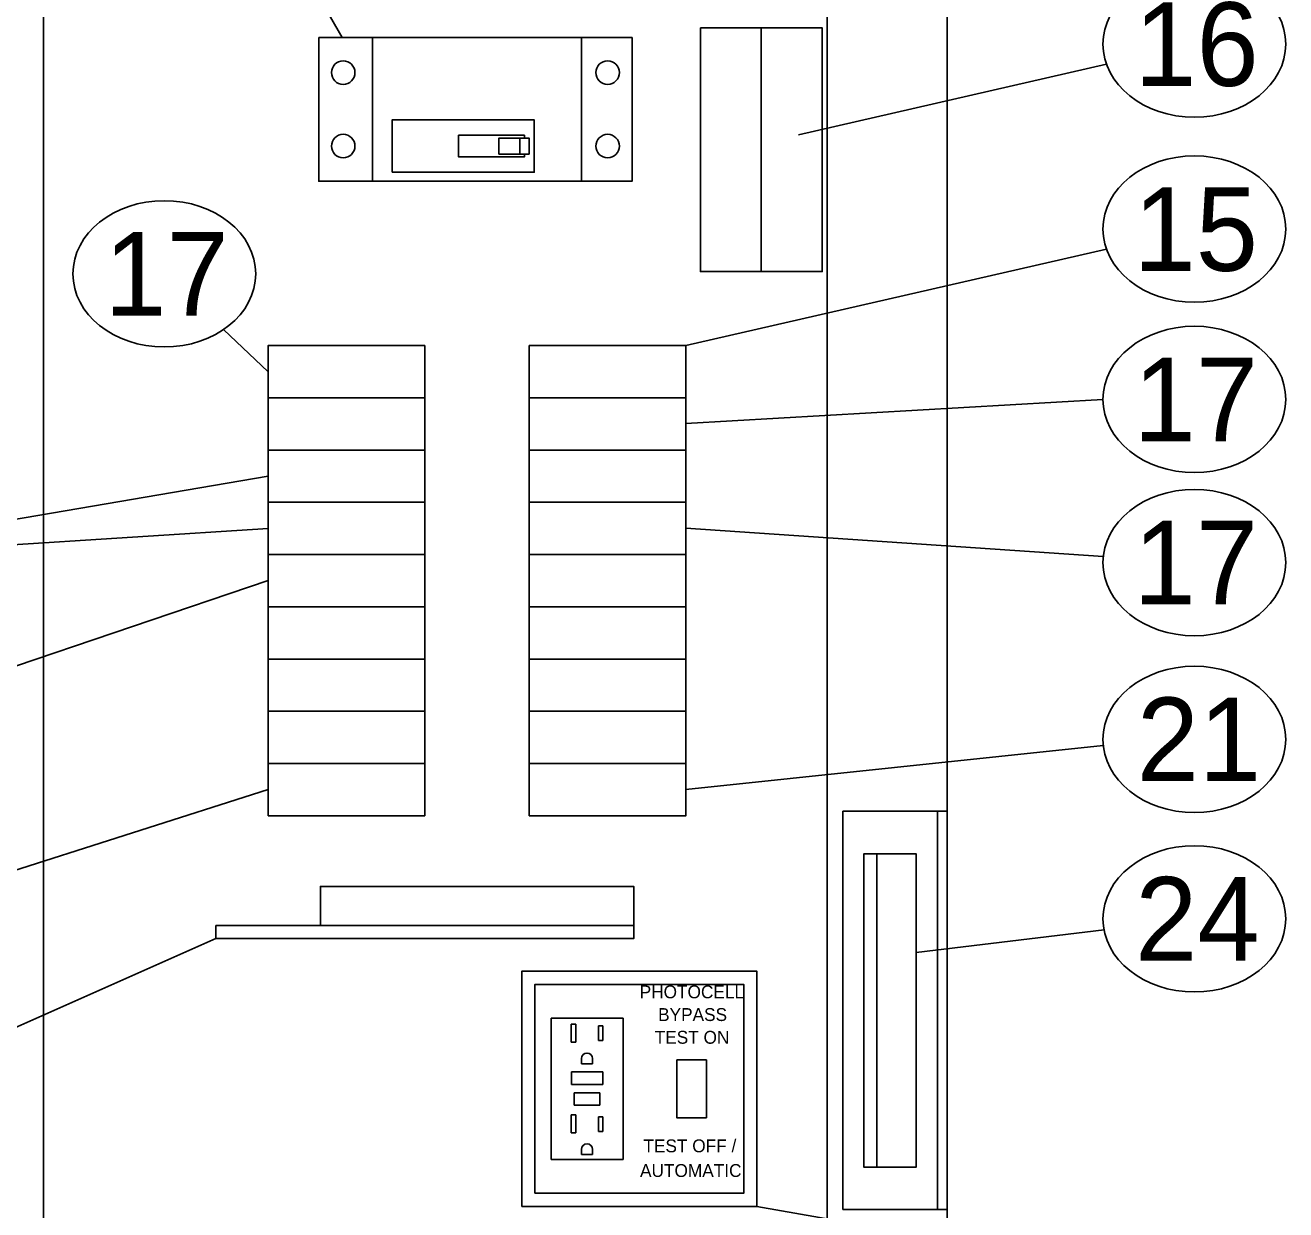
# Model space of a CAD drawing. Extents: x 99862 to 103680, y 99470 to 105076.
# Drawn here: x 102200.2 to 102441.5, y 104648.7 to 104875.4 of the extents above; entities that cross this region are included whole.
import ezdxf

# ---------------------------------------------------------------- set-up
doc = ezdxf.new("R2010")
doc.units = 0
for name, color, linetype in [('Level 1', 7, 'Continuous'), ('Level 15', 7, 'Continuous'), ('Level 20', 7, 'Continuous'), ('Level 40', 7, 'Continuous')]:
    doc.layers.add(name, color=color, linetype=linetype)

msp = doc.modelspace()

# ---------------------------------------------------------------- linework, layer by layer
at = {"layer": 'Level 1'}
for p, q in [((102203.66, 104537.04), (102203.66, 104897.04)), ((102353.66, 104897.04), (102353.66, 104537.04)), ((102294.86, 104853.79), (102294.86, 104850.73)), ((102246.66, 104804.08), (102276.66, 104804.08)), ((102296.66, 104804.08), (102326.66, 104804.08)), ((102296.66, 104784.08), (102326.66, 104784.08)), ((102356.66, 104648.69), (102356.66, 104724.94)), ((102356.66, 104724.94), (102376.66, 104724.94)), ((102374.79, 104648.69), (102374.79, 104724.94)), ((102376.66, 104648.69), (102376.66, 104724.94)), ((102300.84, 104658.31), (102300.84, 104685.31)), ((102300.84, 104685.31), (102314.62, 104685.31)), ((102304.68, 104684.2), (102305.54, 104684.2)), ((102304.68, 104684.2), (102304.68, 104680.74)), ((102305.54, 104684.2), (102305.54, 104680.74)), ((102309.9, 104683.84), (102309.9, 104681.03)), ((102309.9, 104683.84), (102310.77, 104683.84)), ((102310.77, 104683.84), (102310.77, 104681.03)), ((102314.62, 104685.31), (102314.62, 104658.31)), ((102304.68, 104680.74), (102305.54, 104680.74)), ((102309.9, 104681.03), (102310.77, 104681.03)), ((102306.65, 104677.6), (102306.65, 104676.58)), ((102306.65, 104676.58), (102308.78, 104676.58)), ((102308.78, 104677.6), (102308.78, 104676.58)), ((102304.73, 104675.08), (102310.73, 104675.08)), ((102304.73, 104675.08), (102304.73, 104672.62)), ((102310.73, 104675.08), (102310.73, 104672.62)), ((102304.73, 104672.62), (102310.73, 104672.62)), ((102305.23, 104671.06), (102305.23, 104668.66)), ((102305.23, 104671.06), (102310.19, 104671.06)), ((102310.19, 104671.06), (102310.19, 104668.66)), ((102304.68, 104666.82), (102305.54, 104666.82)), ((102304.68, 104666.82), (102304.68, 104663.37)), ((102305.23, 104668.66), (102310.19, 104668.66)), ((102305.54, 104666.82), (102305.54, 104663.37)), ((102309.9, 104666.47), (102309.9, 104663.66)), ((102309.9, 104666.47), (102310.77, 104666.47)), ((102310.77, 104666.47), (102310.77, 104663.66)), ((102304.68, 104663.37), (102305.54, 104663.37)), ((102309.9, 104663.66), (102310.77, 104663.66)), ((102306.65, 104660.22), (102306.65, 104659.21)), ((102306.65, 104659.21), (102308.78, 104659.21)), ((102308.78, 104660.22), (102308.78, 104659.21)), ((102314.62, 104658.31), (102300.84, 104658.31)), ((102356.66, 104648.69), (102376.66, 104648.69))]:
    msp.add_line(p, q, dxfattribs=at)
for points in [[(102256.35, 104873.04), (102316.35, 104873.04), (102316.35, 104845.54), (102256.35, 104845.54)], [(102266.66, 104873.04), (102306.66, 104873.04), (102306.66, 104845.54), (102266.66, 104845.54)], [(102270.41, 104847.26), (102297.6, 104847.26), (102297.6, 104857.26), (102270.41, 104857.26)], [(102296.62, 104850.73), (102290.86, 104850.73), (102290.86, 104853.79), (102296.62, 104853.79)], [(102246.66, 104794.08), (102276.66, 104794.08), (102276.66, 104814.08), (102246.66, 104814.08)], [(102296.66, 104794.08), (102326.66, 104794.08), (102326.66, 104814.08), (102296.66, 104814.08)], [(102246.66, 104784.08), (102276.66, 104784.08), (102276.66, 104794.08), (102246.66, 104794.08)], [(102296.66, 104774.08), (102326.66, 104774.08), (102326.66, 104794.08), (102296.66, 104794.08)], [(102246.66, 104774.08), (102276.66, 104774.08), (102276.66, 104784.08), (102246.66, 104784.08)], [(102246.66, 104764.08), (102276.66, 104764.08), (102276.66, 104774.08), (102246.66, 104774.08)], [(102296.66, 104764.08), (102326.66, 104764.08), (102326.66, 104774.08), (102296.66, 104774.08)], [(102246.66, 104754.08), (102276.66, 104754.08), (102276.66, 104764.08), (102246.66, 104764.08)], [(102296.66, 104754.08), (102326.66, 104754.08), (102326.66, 104764.08), (102296.66, 104764.08)], [(102246.66, 104744.08), (102276.66, 104744.08), (102276.66, 104754.08), (102246.66, 104754.08)], [(102296.66, 104744.08), (102326.66, 104744.08), (102326.66, 104754.08), (102296.66, 104754.08)], [(102246.66, 104734.08), (102276.66, 104734.08), (102276.66, 104744.08), (102246.66, 104744.08)], [(102296.66, 104734.08), (102326.66, 104734.08), (102326.66, 104744.08), (102296.66, 104744.08)], [(102246.66, 104724.08), (102276.66, 104724.08), (102276.66, 104734.08), (102246.66, 104734.08)], [(102296.66, 104724.08), (102326.66, 104724.08), (102326.66, 104734.08), (102296.66, 104734.08)], [(102360.72, 104716.81), (102360.72, 104656.81), (102370.72, 104656.81), (102370.72, 104716.81)], [(102363.22, 104656.81), (102363.22, 104716.81), (102360.72, 104716.81), (102360.72, 104656.81)], [(102316.66, 104703.06), (102236.66, 104703.06), (102236.66, 104700.56), (102316.66, 104700.56)], [(102295.23, 104649.31), (102340.23, 104649.31), (102340.23, 104694.31), (102295.23, 104694.31)], [(102297.73, 104651.81), (102337.73, 104651.81), (102337.73, 104691.81), (102297.73, 104691.81)], [(102324.89, 104677.34), (102324.89, 104666.27), (102330.56, 104666.27), (102330.56, 104677.34)]]:
    msp.add_lwpolyline(points, close=True, dxfattribs=at)
for points in [[(102295.73, 104853.79), (102295.73, 104854.34), (102283.14, 104854.34), (102283.14, 104850.18), (102295.73, 104850.18), (102295.73, 104850.73)], [(102256.66, 104700.56), (102316.66, 104700.56), (102316.66, 104710.56), (102256.66, 104710.56), (102256.66, 104703.06)]]:
    msp.add_lwpolyline(points, dxfattribs=at)
for centre in [(102261.04, 104866.32), (102311.66, 104866.32), (102261.04, 104852.26), (102311.66, 104852.26)]:
    msp.add_circle(centre, 2.25, dxfattribs=at)
for centre in [(102307.72, 104677.6), (102307.72, 104660.22)]:
    msp.add_arc(centre, 1.06, 360, 180, dxfattribs=at)
at = {"layer": 'Level 15'}
for p, q in [((102214.75, 104953.33), (102260.87, 104873.04)), ((102407.16, 104867.93), (102348.18, 104854.42)), ((102407.16, 104832.53), (102326.66, 104814.08)), ((102246.66, 104809.08), (102238.12, 104817.14)), ((102406.48, 104803.77), (102326.66, 104799.14)), ((102246.66, 104789.08), (102152.68, 104773.08)), ((102246.66, 104779.08), (102152.68, 104773.08)), ((102406.54, 104773.72), (102326.66, 104779.14)), ((102246.66, 104769.08), (102142.14, 104733.7)), ((102406.54, 104737.52), (102326.66, 104729.08)), ((102246.66, 104729.08), (102142.28, 104695.84)), ((102236.66, 104700.56), (102141.33, 104658.26)), ((102370.72, 104697.9), (102406.68, 104702.26)), ((102340.23, 104649.31), (102406.88, 104637.63))]:
    msp.add_line(p, q, dxfattribs=at)
at = {"layer": 'Level 20'}
for centre in [(102423.98, 104871.78), (102423.98, 104836.38), (102226.79, 104827.81), (102423.98, 104803.77), (102423.98, 104772.53), (102423.98, 104738.7), (102423.98, 104704.35)]:
    msp.add_ellipse(centre, major_axis=(-17.5, 0), ratio=0.8, dxfattribs=at)
at = {"layer": 'Level 40'}
for p, q in [((102376.66, 104902.94), (102376.66, 104497.94)), ((102341.08, 104874.88), (102341.08, 104828.25))]:
    msp.add_line(p, q, dxfattribs=at)
msp.add_lwpolyline([(102329.42, 104874.88), (102329.42, 104828.25), (102352.74, 104828.25), (102352.74, 104874.88)], close=True, dxfattribs=at)

# ---------------------------------------------------------------- texts
at = {"layer": 'Level 20'}
for s, p in [('16', (102412.5, 104863.78)), ('15', (102412.35, 104828.38)), ('17', (102215.31, 104819.81)), ('17', (102412.35, 104795.77)), ('17', (102412.35, 104764.53)), ('21', (102412.96, 104730.7)), ('24', (102412.65, 104696.35))]:
    msp.add_text(s, height=16, dxfattribs=at).set_placement(p)
at = {"layer": 'Level 40'}
for s, p in [('PHOTOCELL', (102317.79, 104689.14)), ('BYPASS', (102321.32, 104684.79)), ('TEST ON', (102320.67, 104680.44)), ('TEST OFF /', (102318.51, 104659.66)), ('AUTOMATIC', (102317.86, 104654.94))]:
    msp.add_text(s, height=2.467, rotation=360, dxfattribs=at).set_placement(p)

doc.saveas('drawing.dxf')
